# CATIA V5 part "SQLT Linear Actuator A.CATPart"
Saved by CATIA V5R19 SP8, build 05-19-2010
Part number: SQLT Linear Actuator Sup A 9
Publications: "Droite.3", "Plan.2", "Droite.4"
Bounding box of the stored display mesh (mm): x -150 to 150, y 0 to 450, z 750 to 750
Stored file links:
  G:\EU_thinkMotion\CFAO_2010\MMS_groupe3\MMS_groupe3\A reprendre\fovide\fovide\SQLT Linear Actuator A.CATPart
  G:\EU_thinkMotion\CFAO_2010\MMS_groupe3\MMS_groupe3\A reprendre\fovide\fovide\fovide.CATProduct
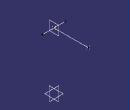
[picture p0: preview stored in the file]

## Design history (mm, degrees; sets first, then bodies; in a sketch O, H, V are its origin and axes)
Set1
  Point1 "Point.A": linked copy from another document
  Point2 "Point.B": linked copy from another document
Set2 "set Linear Actuator A"
  Line1: type PtPt, FirstPoint Point1, SecondPoint Point2
  Plane1: type OffsetPt, RefPlane yz-plane, RefPoint Point1
  Line2: type Normal, RefPoint Point1, RefSkin Plane1, Start -150, End 150
Body1 (main body)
